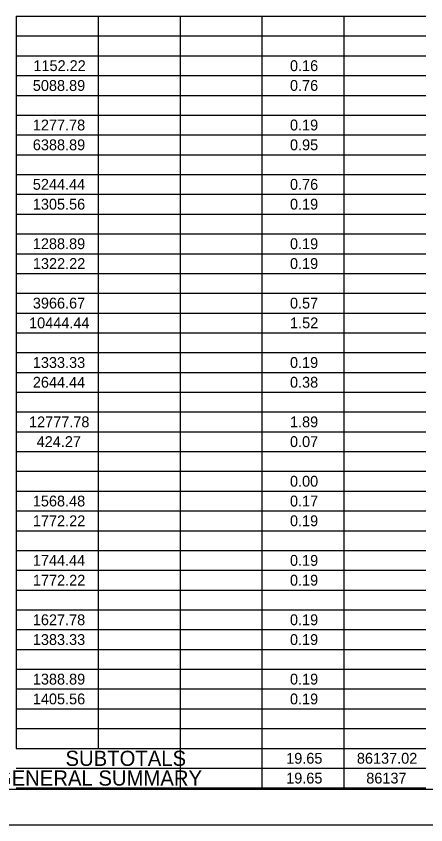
# Model space of a CAD drawing. Extents: x 0 to 34.4, y 0 to 47.
# Drawn here: x 10.58 to 16.38, y 0 to 11.43 of the extents above; entities that cross this region are included whole.
import ezdxf

# ---------------------------------------------------------------- set-up
doc = ezdxf.new("R2010")
doc.units = 0
for name, color, linetype in [('SH_Border', 7, 'Continuous'), ('SH_Cut_Line', 7, 'Continuous'), ('SH_Text', 7, 'Continuous')]:
    doc.layers.add(name, color=color, linetype=linetype)

msp = doc.modelspace()

# ---------------------------------------------------------------- linework, layer by layer
at = {"layer": 'SH_Border'}
msp.add_lwpolyline([(1.5, 21.5), (33.5, 21.5), (33.5, 0.5), (1.5, 0.5)], close=True, dxfattribs=at)
at = {"layer": 'SH_Cut_Line'}
msp.add_lwpolyline([(0, 0), (34, 0), (34, 22), (0, 22)], close=True, dxfattribs=at)
at = {"layer": 'SH_Text'}
for p, q in [((10.584, 11.43), (11.743, 11.43)), ((10.584, 11.43), (10.584, 10.311)), ((11.743, 11.43), (14.061, 11.43)), ((11.743, 11.43), (11.743, 10.311)), ((12.902, 11.43), (12.902, 10.311)), ((14.061, 11.43), (15.22, 11.43)), ((14.061, 11.43), (14.061, 10.311)), ((15.22, 11.43), (16.378, 11.43)), ((15.22, 11.43), (15.22, 10.311)), ((10.584, 11.15), (11.743, 11.15)), ((11.743, 11.15), (14.061, 11.15)), ((14.061, 11.15), (15.22, 11.15)), ((15.22, 11.15), (16.378, 11.15)), ((10.584, 10.871), (11.743, 10.871)), ((11.743, 10.871), (14.061, 10.871)), ((14.061, 10.871), (15.22, 10.871)), ((15.22, 10.871), (16.378, 10.871)), ((10.584, 10.591), (11.743, 10.591)), ((11.743, 10.591), (14.061, 10.591)), ((14.061, 10.591), (15.22, 10.591)), ((15.22, 10.591), (16.378, 10.591)), ((10.584, 10.311), (11.743, 10.311)), ((10.584, 10.311), (10.584, 9.752)), ((11.743, 10.311), (14.061, 10.311)), ((11.743, 10.311), (11.743, 9.752)), ((12.902, 10.311), (12.902, 9.752)), ((14.061, 10.311), (15.22, 10.311)), ((14.061, 10.311), (14.061, 9.752)), ((15.22, 10.311), (16.378, 10.311)), ((15.22, 10.311), (15.22, 9.752)), ((10.584, 10.031), (11.743, 10.031)), ((11.743, 10.031), (14.061, 10.031)), ((14.061, 10.031), (15.22, 10.031)), ((15.22, 10.031), (16.378, 10.031)), ((10.584, 9.752), (11.743, 9.752)), ((10.584, 9.752), (10.584, 9.472)), ((11.743, 9.752), (14.061, 9.752)), ((11.743, 9.752), (11.743, 9.472)), ((12.902, 9.752), (12.902, 9.472)), ((14.061, 9.752), (15.22, 9.752)), ((14.061, 9.752), (14.061, 9.472)), ((15.22, 9.752), (16.378, 9.752)), ((15.22, 9.752), (15.22, 9.472)), ((10.584, 9.472), (11.743, 9.472)), ((10.584, 9.472), (10.584, 9.192)), ((11.743, 9.472), (14.061, 9.472)), ((11.743, 9.472), (11.743, 9.192)), ((12.902, 9.472), (12.902, 9.192)), ((14.061, 9.472), (15.22, 9.472)), ((14.061, 9.472), (14.061, 9.192)), ((15.22, 9.472), (16.378, 9.472)), ((15.22, 9.472), (15.22, 9.192)), ((10.584, 9.192), (11.743, 9.192)), ((10.584, 9.192), (10.584, 8.913)), ((11.743, 9.192), (14.061, 9.192)), ((11.743, 9.192), (11.743, 8.913)), ((12.902, 9.192), (12.902, 8.913)), ((14.061, 9.192), (15.22, 9.192)), ((14.061, 9.192), (14.061, 8.913)), ((15.22, 9.192), (16.378, 9.192)), ((15.22, 9.192), (15.22, 8.913)), ((10.584, 8.913), (11.743, 8.913)), ((10.584, 8.913), (10.584, 8.633)), ((11.743, 8.913), (14.061, 8.913)), ((11.743, 8.913), (11.743, 8.633)), ((12.902, 8.913), (12.902, 8.633)), ((14.061, 8.913), (15.22, 8.913)), ((14.061, 8.913), (14.061, 8.633)), ((15.22, 8.913), (16.378, 8.913)), ((15.22, 8.913), (15.22, 8.633)), ((10.584, 8.633), (11.743, 8.633)), ((10.584, 8.633), (10.584, 8.353)), ((11.743, 8.633), (14.061, 8.633)), ((11.743, 8.633), (11.743, 8.353)), ((12.902, 8.633), (12.902, 8.353)), ((14.061, 8.633), (15.22, 8.633)), ((14.061, 8.633), (14.061, 8.353)), ((15.22, 8.633), (16.378, 8.633)), ((15.22, 8.633), (15.22, 8.353)), ((10.584, 8.353), (11.743, 8.353)), ((10.584, 8.353), (10.584, 8.073)), ((11.743, 8.353), (14.061, 8.353)), ((11.743, 8.353), (11.743, 8.073)), ((12.902, 8.353), (12.902, 8.073)), ((14.061, 8.353), (15.22, 8.353)), ((14.061, 8.353), (14.061, 8.073)), ((15.22, 8.353), (16.378, 8.353)), ((15.22, 8.353), (15.22, 8.073)), ((10.584, 8.073), (11.743, 8.073)), ((10.584, 8.073), (10.584, 7.794)), ((11.743, 8.073), (14.061, 8.073)), ((11.743, 8.073), (11.743, 7.794)), ((12.902, 8.073), (12.902, 7.794)), ((14.061, 8.073), (15.22, 8.073)), ((14.061, 8.073), (14.061, 7.794)), ((15.22, 8.073), (16.378, 8.073)), ((15.22, 8.073), (15.22, 7.794)), ((10.584, 7.794), (11.743, 7.794)), ((10.584, 7.794), (10.584, 7.514)), ((11.743, 7.794), (14.061, 7.794)), ((11.743, 7.794), (11.743, 7.514)), ((12.902, 7.794), (12.902, 7.514)), ((14.061, 7.794), (15.22, 7.794)), ((14.061, 7.794), (14.061, 7.514)), ((15.22, 7.794), (16.378, 7.794)), ((15.22, 7.794), (15.22, 7.514)), ((10.584, 7.514), (11.743, 7.514)), ((10.584, 7.514), (10.584, 7.234)), ((11.743, 7.514), (14.061, 7.514)), ((11.743, 7.514), (11.743, 7.234)), ((12.902, 7.514), (12.902, 7.234)), ((14.061, 7.514), (15.22, 7.514)), ((14.061, 7.514), (14.061, 7.234)), ((15.22, 7.514), (16.378, 7.514)), ((15.22, 7.514), (15.22, 7.234)), ((10.584, 7.234), (11.743, 7.234)), ((10.584, 7.234), (10.584, 6.955)), ((11.743, 7.234), (14.061, 7.234)), ((11.743, 7.234), (11.743, 6.955)), ((12.902, 7.234), (12.902, 6.955)), ((14.061, 7.234), (15.22, 7.234)), ((14.061, 7.234), (14.061, 6.955)), ((15.22, 7.234), (16.378, 7.234)), ((15.22, 7.234), (15.22, 6.955)), ((10.584, 6.955), (11.743, 6.955)), ((10.584, 6.955), (10.584, 6.675)), ((11.743, 6.955), (14.061, 6.955)), ((11.743, 6.955), (11.743, 6.675)), ((12.902, 6.955), (12.902, 6.675)), ((14.061, 6.955), (15.22, 6.955)), ((14.061, 6.955), (14.061, 6.675)), ((15.22, 6.955), (16.378, 6.955)), ((15.22, 6.955), (15.22, 6.675)), ((10.584, 6.675), (11.743, 6.675)), ((10.584, 6.675), (10.584, 6.395)), ((11.743, 6.675), (14.061, 6.675)), ((11.743, 6.675), (11.743, 6.395)), ((12.902, 6.675), (12.902, 6.395)), ((14.061, 6.675), (15.22, 6.675)), ((14.061, 6.675), (14.061, 6.395)), ((15.22, 6.675), (16.378, 6.675)), ((15.22, 6.675), (15.22, 6.395)), ((10.584, 6.395), (11.743, 6.395)), ((10.584, 6.395), (10.584, 6.115)), ((11.743, 6.395), (14.061, 6.395)), ((11.743, 6.395), (11.743, 6.115)), ((12.902, 6.395), (12.902, 6.115)), ((14.061, 6.395), (15.22, 6.395)), ((14.061, 6.395), (14.061, 6.115)), ((15.22, 6.395), (16.378, 6.395)), ((15.22, 6.395), (15.22, 6.115)), ((10.584, 6.115), (11.743, 6.115)), ((10.584, 6.115), (10.584, 5.836)), ((11.743, 6.115), (14.061, 6.115)), ((11.743, 6.115), (11.743, 5.836)), ((12.902, 6.115), (12.902, 5.836)), ((14.061, 6.115), (15.22, 6.115)), ((14.061, 6.115), (14.061, 5.836)), ((15.22, 6.115), (16.378, 6.115)), ((15.22, 6.115), (15.22, 5.836)), ((10.584, 5.836), (11.743, 5.836)), ((10.584, 5.836), (10.584, 5.556)), ((11.743, 5.836), (14.061, 5.836)), ((11.743, 5.836), (11.743, 5.556)), ((12.902, 5.836), (12.902, 5.556)), ((14.061, 5.836), (15.22, 5.836)), ((14.061, 5.836), (14.061, 5.556)), ((15.22, 5.836), (16.378, 5.836)), ((15.22, 5.836), (15.22, 5.556)), ((10.584, 5.556), (11.743, 5.556)), ((10.584, 5.556), (10.584, 4.997)), ((11.743, 5.556), (14.061, 5.556)), ((11.743, 5.556), (11.743, 4.997)), ((12.902, 5.556), (12.902, 4.997)), ((14.061, 5.556), (15.22, 5.556)), ((14.061, 5.556), (14.061, 4.997)), ((15.22, 5.556), (16.378, 5.556)), ((15.22, 5.556), (15.22, 4.997)), ((10.584, 5.276), (11.743, 5.276)), ((11.743, 5.276), (14.061, 5.276)), ((14.061, 5.276), (15.22, 5.276)), ((15.22, 5.276), (16.378, 5.276)), ((10.584, 4.997), (11.743, 4.997)), ((10.584, 4.997), (10.584, 4.717)), ((11.743, 4.997), (14.061, 4.997)), ((11.743, 4.997), (11.743, 4.717)), ((12.902, 4.997), (12.902, 4.717)), ((14.061, 4.997), (15.22, 4.997)), ((14.061, 4.997), (14.061, 4.717)), ((15.22, 4.997), (16.378, 4.997)), ((15.22, 4.997), (15.22, 4.717)), ((10.584, 4.717), (11.743, 4.717)), ((10.584, 4.717), (10.584, 4.437)), ((11.743, 4.717), (14.061, 4.717)), ((11.743, 4.717), (11.743, 4.437)), ((12.902, 4.717), (12.902, 4.437)), ((14.061, 4.717), (15.22, 4.717)), ((14.061, 4.717), (14.061, 4.437)), ((15.22, 4.717), (16.378, 4.717)), ((15.22, 4.717), (15.22, 4.437)), ((10.584, 4.437), (11.743, 4.437)), ((10.584, 4.437), (10.584, 4.157)), ((11.743, 4.437), (14.061, 4.437)), ((11.743, 4.437), (11.743, 4.157)), ((12.902, 4.437), (12.902, 4.157)), ((14.061, 4.437), (15.22, 4.437)), ((14.061, 4.437), (14.061, 4.157)), ((15.22, 4.437), (16.378, 4.437)), ((15.22, 4.437), (15.22, 4.157)), ((10.584, 4.157), (11.743, 4.157)), ((10.584, 4.157), (10.584, 3.598)), ((11.743, 4.157), (14.061, 4.157)), ((11.743, 4.157), (11.743, 3.598)), ((12.902, 4.157), (12.902, 3.598)), ((14.061, 4.157), (15.22, 4.157)), ((14.061, 4.157), (14.061, 3.598)), ((15.22, 4.157), (16.378, 4.157)), ((15.22, 4.157), (15.22, 3.598)), ((10.584, 3.878), (11.743, 3.878)), ((11.743, 3.878), (14.061, 3.878)), ((14.061, 3.878), (15.22, 3.878)), ((15.22, 3.878), (16.378, 3.878)), ((10.584, 3.598), (11.743, 3.598)), ((10.584, 3.598), (10.584, 3.318)), ((11.743, 3.598), (14.061, 3.598)), ((11.743, 3.598), (11.743, 3.318)), ((12.902, 3.598), (12.902, 3.318)), ((14.061, 3.598), (15.22, 3.598)), ((14.061, 3.598), (14.061, 3.318)), ((15.22, 3.598), (16.378, 3.598)), ((15.22, 3.598), (15.22, 3.318)), ((10.584, 3.318), (11.743, 3.318)), ((10.584, 3.318), (10.584, 3.038)), ((11.743, 3.318), (14.061, 3.318)), ((11.743, 3.318), (11.743, 3.038)), ((12.902, 3.318), (12.902, 3.038)), ((14.061, 3.318), (15.22, 3.318)), ((14.061, 3.318), (14.061, 3.038)), ((15.22, 3.318), (16.378, 3.318)), ((15.22, 3.318), (15.22, 3.038)), ((10.584, 3.038), (11.743, 3.038)), ((10.584, 3.038), (10.584, 2.759)), ((11.743, 3.038), (14.061, 3.038)), ((11.743, 3.038), (11.743, 2.759)), ((12.902, 3.038), (12.902, 2.759)), ((14.061, 3.038), (15.22, 3.038)), ((14.061, 3.038), (14.061, 2.759)), ((15.22, 3.038), (16.378, 3.038)), ((15.22, 3.038), (15.22, 2.759)), ((10.584, 2.759), (11.743, 2.759)), ((10.584, 2.759), (10.584, 2.199)), ((11.743, 2.759), (14.061, 2.759)), ((11.743, 2.759), (11.743, 2.199)), ((12.902, 2.759), (12.902, 2.199)), ((14.061, 2.759), (15.22, 2.759)), ((14.061, 2.759), (14.061, 2.199)), ((15.22, 2.759), (16.378, 2.759)), ((15.22, 2.759), (15.22, 2.199)), ((10.584, 2.479), (11.743, 2.479)), ((11.743, 2.479), (14.061, 2.479)), ((14.061, 2.479), (15.22, 2.479)), ((15.22, 2.479), (16.378, 2.479)), ((10.584, 2.199), (11.743, 2.199)), ((10.584, 2.199), (10.584, 1.92)), ((11.743, 2.199), (14.061, 2.199)), ((11.743, 2.199), (11.743, 1.92)), ((12.902, 2.199), (12.902, 1.92)), ((14.061, 2.199), (15.22, 2.199)), ((14.061, 2.199), (14.061, 1.92)), ((15.22, 2.199), (16.378, 2.199)), ((15.22, 2.199), (15.22, 1.92)), ((10.584, 1.92), (11.743, 1.92)), ((10.584, 1.92), (10.584, 1.64)), ((11.743, 1.92), (14.061, 1.92)), ((11.743, 1.92), (11.743, 1.64)), ((12.902, 1.92), (12.902, 1.64)), ((14.061, 1.92), (15.22, 1.92)), ((14.061, 1.92), (14.061, 1.64)), ((15.22, 1.92), (16.378, 1.92)), ((15.22, 1.92), (15.22, 1.64)), ((10.584, 1.64), (11.743, 1.64)), ((10.584, 1.64), (10.584, 1.36)), ((11.743, 1.64), (14.061, 1.64)), ((11.743, 1.64), (11.743, 1.36)), ((12.902, 1.64), (12.902, 1.36)), ((14.061, 1.64), (15.22, 1.64)), ((14.061, 1.64), (14.061, 1.36)), ((15.22, 1.64), (16.378, 1.64)), ((15.22, 1.64), (15.22, 1.36)), ((10.584, 1.36), (11.743, 1.36)), ((10.584, 1.36), (10.584, 1.08)), ((11.743, 1.36), (14.061, 1.36)), ((11.743, 1.36), (11.743, 1.08)), ((12.902, 1.36), (12.902, 0.801)), ((14.061, 1.36), (15.22, 1.36)), ((14.061, 1.36), (14.061, 0.801)), ((15.22, 1.36), (16.378, 1.36)), ((15.22, 1.36), (15.22, 0.801)), ((10.584, 1.08), (11.743, 1.08)), ((11.743, 1.08), (14.061, 1.08)), ((14.061, 1.08), (15.22, 1.08)), ((15.22, 1.08), (16.378, 1.08)), ((10.584, 0.801), (11.743, 0.801)), ((11.743, 0.801), (14.061, 0.801)), ((12.902, 0.801), (12.902, 0.521)), ((14.061, 0.801), (15.22, 0.801)), ((14.061, 0.801), (14.061, 0.521)), ((15.22, 0.801), (16.378, 0.801)), ((15.22, 0.801), (15.22, 0.521)), ((10.584, 0.521), (11.743, 0.521)), ((11.743, 0.521), (14.061, 0.521)), ((14.061, 0.521), (15.22, 0.521)), ((15.22, 0.521), (16.378, 0.521))]:
    msp.add_line(p, q, dxfattribs=at)

# ---------------------------------------------------------------- texts
for s, height, p in [('1152.22', 0.1532, (10.828, 10.654)), ('0.16', 0.1532, (14.457, 10.654)), ('5088.89', 0.1532, (10.82, 10.374)), ('0.76', 0.1532, (14.457, 10.374)), ('1277.78', 0.1532, (10.82, 9.815)), ('0.19', 0.1532, (14.457, 9.815)), ('6388.89', 0.1532, (10.82, 9.535)), ('0.95', 0.1532, (14.457, 9.535)), ('5244.44', 0.1532, (10.82, 8.976)), ('0.76', 0.1532, (14.457, 8.976)), ('1305.56', 0.1532, (10.82, 8.696)), ('0.19', 0.1532, (14.457, 8.696)), ('1288.89', 0.1532, (10.82, 8.137)), ('0.19', 0.1532, (14.457, 8.137)), ('1322.22', 0.1532, (10.821, 7.857)), ('0.19', 0.1532, (14.457, 7.857)), ('3966.67', 0.1532, (10.82, 7.298)), ('0.57', 0.1532, (14.457, 7.298)), ('10444.44', 0.1532, (10.767, 7.018)), ('1.52', 0.1532, (14.458, 7.018)), ('1333.33', 0.1532, (10.82, 6.458)), ('0.19', 0.1532, (14.457, 6.458)), ('2644.44', 0.1532, (10.82, 6.179)), ('0.38', 0.1532, (14.457, 6.179)), ('12777.78', 0.1532, (10.766, 5.619)), ('1.89', 0.1532, (14.457, 5.619)), ('424.27', 0.1532, (10.874, 5.34)), ('0.07', 0.1532, (14.457, 5.34)), ('0.00', 0.1532, (14.457, 4.78)), ('1568.48', 0.1532, (10.82, 4.5)), ('0.17', 0.1532, (14.457, 4.5)), ('1772.22', 0.1532, (10.821, 4.221)), ('0.19', 0.1532, (14.457, 4.221)), ('1744.44', 0.1532, (10.82, 3.661)), ('0.19', 0.1532, (14.457, 3.661)), ('1772.22', 0.1532, (10.821, 3.381)), ('0.19', 0.1532, (14.457, 3.381)), ('1627.78', 0.1532, (10.82, 2.822)), ('0.19', 0.1532, (14.457, 2.822)), ('1383.33', 0.1532, (10.82, 2.542)), ('0.19', 0.1532, (14.457, 2.542)), ('1388.89', 0.1532, (10.82, 1.983)), ('0.19', 0.1532, (14.457, 1.983)), ('1405.56', 0.1532, (10.82, 1.703)), ('0.19', 0.1532, (14.457, 1.703)), ('SUBTOTALS', 0.2145, (11.282, 0.833)), ('19.65', 0.1532, (14.403, 0.864)), ('86137.02', 0.1532, (15.403, 0.864)), ('TOTALS CARRIED TO GENERAL SUMMARY', 0.21445, (7.254, 0.554)), ('19.65', 0.1532, (14.403, 0.584)), ('86137', 0.1532, (15.536, 0.584))]:
    msp.add_text(s, height=height, dxfattribs=at).set_placement(p)

doc.saveas('drawing.dxf')
